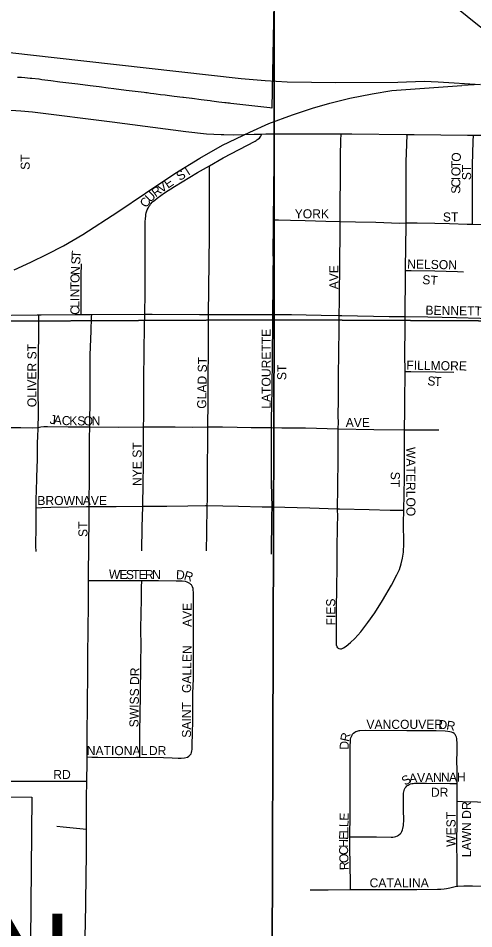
# Model space of a CAD drawing. Extents: x -9.1 to 34, y -3.1 to 22.
# Drawn here: x 3.961 to 4.437, y 19.14 to 20.093 of the extents above; entities that cross this region are included whole.
import ezdxf

# ---------------------------------------------------------------- set-up
doc = ezdxf.new("R2010")
doc.units = 0
for name, color, linetype in [('GM_X_City_Street', 7, 'Continuous'), ('GM_X_City_Street_Text', 7, 'Continuous'), ('GM_X_Corporation', 7, 'Continuous'), ('GM_X_Corporation_Text', 7, 'Continuous'), ('GM_X_Rail_Line', 7, 'Continuous'), ('GM_X_Section', 7, 'Continuous'), ('GM_X_State_Route', 7, 'Continuous')]:
    doc.layers.add(name, color=color, linetype=linetype)

msp = doc.modelspace()

# ---------------------------------------------------------------- linework, layer by layer
at = {"layer": 'GM_X_City_Street'}
for points in [[(4.16087, 19.93855), (4.17537, 19.94691), (4.2085, 19.96427), (4.20954, 19.96483), (4.21052, 19.9655), (4.21156, 19.96621), (4.21304, 19.96755), (4.21386, 19.96851), (4.21448, 19.96951), (4.21581, 19.97174)], [(4.22794, 19.88188), (4.2279, 19.88887), (4.22823, 19.90439), (4.22821, 19.9137), (4.22845, 19.94165), (4.22843, 19.96027), (4.22841, 19.9719)], [(4.29745, 19.88035), (4.29745, 19.88421), (4.29758, 19.89662), (4.29782, 19.92767), (4.29787, 19.94941), (4.29836, 19.96492), (4.29857, 19.97193)], [(4.36671, 19.87867), (4.36667, 19.90228), (4.36673, 19.94262), (4.36723, 19.96124), (4.3675, 19.97124)], [(4.43592, 19.87741), (4.43603, 19.88408), (4.43613, 19.89033), (4.43602, 19.89958), (4.43608, 19.93955), (4.43678, 19.96407), (4.43696, 19.9705)], [(4.09572, 19.89225), (4.09661, 19.89415), (4.09754, 19.89584), (4.09832, 19.89707), (4.09934, 19.89839), (4.10144, 19.90068), (4.10368, 19.9027), (4.1061, 19.90464), (4.11382, 19.91011), (4.1243, 19.91687), (4.14836, 19.93134), (4.16087, 19.93855)], [(4.16001, 19.78304), (4.16023, 19.80993), (4.16091, 19.86603), (4.16097, 19.90967), (4.16088, 19.93458), (4.16087, 19.93855)], [(4.09319, 19.78325), (4.09345, 19.80552), (4.09346, 19.85212), (4.0937, 19.88008), (4.09381, 19.88302), (4.09415, 19.88626), (4.09433, 19.88764), (4.0947, 19.88931), (4.09572, 19.89225)], [(4.22713, 19.78295), (4.22736, 19.81436), (4.22739, 19.82989), (4.22767, 19.83919), (4.22764, 19.84851), (4.22797, 19.87645), (4.22794, 19.88188)], [(4.22794, 19.88188), (4.23317, 19.88179), (4.24552, 19.88159), (4.26093, 19.88133), (4.28252, 19.88059), (4.29745, 19.88035)], [(4.2967, 19.78181), (4.2968, 19.79726), (4.29716, 19.84073), (4.29746, 19.86557), (4.29745, 19.88035)], [(4.29745, 19.88035), (4.31351, 19.87987), (4.33505, 19.87934), (4.35965, 19.87864), (4.36671, 19.87867)], [(4.36588, 19.82907), (4.36629, 19.85583), (4.36672, 19.87439), (4.36671, 19.87867)], [(4.36671, 19.87867), (4.37818, 19.87872), (4.39664, 19.87855), (4.41194, 19.87829), (4.43053, 19.87758), (4.43592, 19.87741)], [(4.43592, 19.87741), (4.44582, 19.87712), (4.44887, 19.8771), (4.45033, 19.87715), (4.45191, 19.87728), (4.45343, 19.87754), (4.45483, 19.87803), (4.45618, 19.87867), (4.45746, 19.87949)], [(4.0267, 19.7829), (4.02667, 19.79032), (4.02662, 19.80862), (4.02665, 19.82387), (4.02719, 19.83608)], [(4.36566, 19.78066), (4.36577, 19.82494), (4.36588, 19.82907)], [(4.36588, 19.82907), (4.37198, 19.82893), (4.39643, 19.82844), (4.40848, 19.82809), (4.42032, 19.82788), (4.4265, 19.82747)], [(3.92629, 19.7819), (3.98068, 19.78246), (3.98245, 19.78248)], [(3.98163, 19.66474), (3.98172, 19.66863), (3.9819, 19.67452), (3.98207, 19.68431), (3.98182, 19.69991), (3.98186, 19.70301), (3.98182, 19.71222), (3.982, 19.71799), (3.98209, 19.72448), (3.98195, 19.73069), (3.98199, 19.73594), (3.98205, 19.74348), (3.98209, 19.74816), (3.98227, 19.75533), (3.98246, 19.76784), (3.98247, 19.77436), (3.98248, 19.77747), (3.98248, 19.78124), (3.98245, 19.78248)], [(3.98245, 19.78248), (3.9847, 19.78251), (4.02034, 19.78287), (4.0267, 19.7829)], [(4.0267, 19.7829), (4.03769, 19.78296)], [(4.03557, 19.66525), (4.03562, 19.66917), (4.03593, 19.69402), (4.03616, 19.74067), (4.03697, 19.76557), (4.03756, 19.77996), (4.03769, 19.78296)], [(4.03769, 19.78296), (4.09319, 19.78325)], [(4.09199, 19.66521), (4.09212, 19.6751), (4.09226, 19.69371), (4.09235, 19.71544), (4.09305, 19.77135), (4.09319, 19.78325)], [(4.09319, 19.78325), (4.10098, 19.78328), (4.15058, 19.78305), (4.16001, 19.78304)], [(4.15928, 19.6652), (4.1594, 19.69154), (4.1596, 19.7102), (4.15975, 19.75072), (4.16001, 19.78304)], [(4.16001, 19.78304), (4.21571, 19.78302), (4.22713, 19.78295)], [(4.22584, 19.66451), (4.22582, 19.6685), (4.22618, 19.69331), (4.22628, 19.69952), (4.22632, 19.70262), (4.22646, 19.71191), (4.22643, 19.71501), (4.22679, 19.72743), (4.22664, 19.73364), (4.22682, 19.74295), (4.22704, 19.77089), (4.22713, 19.78295)], [(4.22713, 19.78295), (4.24671, 19.78284), (4.26218, 19.78255), (4.27766, 19.78236), (4.2967, 19.78181)], [(4.29565, 19.6633), (4.29567, 19.67012), (4.29559, 19.67622), (4.29575, 19.69482), (4.2958, 19.70412), (4.29575, 19.71654), (4.2962, 19.74448), (4.29662, 19.76621), (4.2967, 19.78181)], [(4.2967, 19.78181), (4.29934, 19.78173), (4.34897, 19.78091), (4.36566, 19.78066)], [(4.36552, 19.72333), (4.36538, 19.74122), (4.36563, 19.76915), (4.36566, 19.78066)], [(4.36566, 19.78066), (4.38924, 19.78031), (4.41939, 19.77962), (4.44389, 19.77921), (4.47645, 19.7787)], [(4.36492, 19.66215), (4.36508, 19.68294), (4.36522, 19.69512), (4.36555, 19.71954), (4.36552, 19.72333)], [(4.36552, 19.72333), (4.37163, 19.72323), (4.39722, 19.72281), (4.4164, 19.72265)], [(3.92585, 19.66479), (3.93605, 19.66472), (3.96356, 19.66453), (3.97601, 19.66448), (3.98163, 19.66474)], [(3.97966, 19.58071), (3.97966, 19.58161), (3.97966, 19.59097), (3.9799, 19.5972), (3.98026, 19.61278), (3.98087, 19.6314), (3.98083, 19.63764), (3.981, 19.64385), (3.98109, 19.64963), (3.98127, 19.65434), (3.98163, 19.66474)], [(3.98163, 19.66474), (3.98461, 19.66528), (3.98757, 19.66555), (3.99133, 19.66555), (4.01299, 19.66547), (4.03475, 19.66525), (4.03557, 19.66525)], [(4.03516, 19.58195), (4.03526, 19.61636), (4.03538, 19.63192), (4.03545, 19.65366), (4.03557, 19.66525)], [(4.03557, 19.66525), (4.06581, 19.66494), (4.09199, 19.66521)], [(4.09104, 19.58223), (4.09139, 19.60657), (4.09176, 19.62513), (4.09185, 19.6534), (4.09199, 19.66521)], [(4.09199, 19.66521), (4.09688, 19.66526), (4.12485, 19.66534), (4.14346, 19.66519), (4.15928, 19.6652)], [(4.15857, 19.5829), (4.15875, 19.58877), (4.15885, 19.62304), (4.15922, 19.65106), (4.15928, 19.6652)], [(4.15928, 19.6652), (4.17444, 19.66522), (4.18984, 19.66492), (4.2045, 19.66466), (4.21475, 19.66463), (4.22584, 19.66451)], [(4.22628, 19.58154), (4.22629, 19.58159), (4.22564, 19.60641), (4.22588, 19.64367), (4.22584, 19.66451)], [(4.22584, 19.66451), (4.23649, 19.66439), (4.26132, 19.66419), (4.29547, 19.6633), (4.29565, 19.6633)], [(4.29482, 19.57966), (4.29489, 19.58433), (4.29495, 19.58842), (4.29501, 19.59314), (4.29506, 19.59698), (4.29514, 19.60228), (4.2952, 19.60822), (4.29526, 19.61467), (4.29531, 19.61971), (4.29534, 19.62367), (4.29538, 19.62776), (4.29542, 19.63171), (4.29546, 19.63645), (4.2955, 19.6413), (4.29554, 19.64526), (4.2956, 19.65161), (4.29565, 19.66086), (4.29565, 19.6633)], [(4.29565, 19.6633), (4.33272, 19.66265), (4.36492, 19.66215)], [(4.36401, 19.57821), (4.36486, 19.61181), (4.36484, 19.65206), (4.36492, 19.66215)], [(4.36492, 19.66215), (4.36991, 19.66207), (4.3915, 19.6624), (4.4008, 19.6623)], [(3.97974, 19.53496), (3.9794, 19.54068), (3.9794, 19.54494), (3.97949, 19.55675), (3.97967, 19.56077), (3.97966, 19.56529), (3.9797, 19.56915), (3.97966, 19.58071)], [(3.97966, 19.58071), (3.98566, 19.58093), (3.99497, 19.58127), (4.03232, 19.58193), (4.03516, 19.58195)], [(4.0344, 19.50475), (4.03445, 19.51058), (4.03513, 19.56969), (4.03516, 19.58195)], [(4.03516, 19.58195), (4.06345, 19.58211), (4.09104, 19.58223)], [(4.09005, 19.53552), (4.0906, 19.56032), (4.09103, 19.58204), (4.09104, 19.58223)], [(4.09104, 19.58223), (4.11636, 19.58235), (4.13816, 19.58263), (4.15683, 19.58293), (4.15857, 19.5829)], [(4.15791, 19.53577), (4.15798, 19.55453), (4.15857, 19.5829)], [(4.15857, 19.5829), (4.19106, 19.58227), (4.21596, 19.5818), (4.22628, 19.58154)], [(4.2256, 19.53214), (4.22579, 19.53817), (4.22582, 19.54187), (4.22586, 19.54542), (4.2259, 19.54995), (4.22594, 19.55367), (4.22613, 19.56298), (4.22595, 19.57196), (4.22628, 19.58154)], [(4.22628, 19.58154), (4.26571, 19.58055), (4.29482, 19.57966)], [(4.29835, 19.43274), (4.2967, 19.43312), (4.29593, 19.43343), (4.29508, 19.43405), (4.29427, 19.43522), (4.29391, 19.43683), (4.29376, 19.43846), (4.29371, 19.4413), (4.29374, 19.45372), (4.29367, 19.45675), (4.29369, 19.45976), (4.2936, 19.46584), (4.29369, 19.47511), (4.29402, 19.49684), (4.29433, 19.51855), (4.29433, 19.53717), (4.29489, 19.56199), (4.29498, 19.5713), (4.29482, 19.57966)], [(4.29482, 19.57966), (4.29682, 19.5796), (4.32792, 19.57873), (4.34971, 19.57831), (4.35465, 19.57834), (4.36401, 19.57821)], [(4.29835, 19.43274), (4.3011, 19.43409), (4.30368, 19.43577), (4.3085, 19.43959), (4.31295, 19.44385), (4.31912, 19.45073), (4.32665, 19.4605), (4.33369, 19.47062), (4.3419, 19.48366), (4.3512, 19.49964), (4.35696, 19.51054), (4.35952, 19.51614), (4.36151, 19.52197), (4.3629, 19.52797), (4.36372, 19.53407), (4.36409, 19.5433), (4.36383, 19.56487), (4.36401, 19.57821)], [(4.03279, 19.32007), (4.03285, 19.34259), (4.03357, 19.40793), (4.03381, 19.42659), (4.03419, 19.47947), (4.0344, 19.50475)], [(4.0344, 19.50475), (4.04214, 19.5047), (4.06392, 19.50453), (4.08998, 19.50451)], [(4.08808, 19.31959), (4.08807, 19.32443), (4.08805, 19.33125), (4.08803, 19.336), (4.08802, 19.33997), (4.08815, 19.34918), (4.08825, 19.36154), (4.08891, 19.41407), (4.08915, 19.42019), (4.08937, 19.43568), (4.08907, 19.45421), (4.08975, 19.48506), (4.0899, 19.49743), (4.08998, 19.50451)], [(4.08998, 19.50451), (4.1075, 19.5045), (4.12617, 19.50434), (4.13237, 19.50413), (4.13542, 19.50373), (4.13724, 19.50319), (4.13844, 19.50263), (4.13992, 19.50172), (4.14152, 19.50056)], [(4.13784, 19.31979), (4.13938, 19.32071), (4.14078, 19.32203), (4.14162, 19.32323), (4.14218, 19.32463), (4.14245, 19.32624), (4.1426, 19.32785), (4.14288, 19.3308), (4.14327, 19.34652), (4.14344, 19.35575), (4.14346, 19.3681), (4.14357, 19.37722), (4.14355, 19.38653), (4.14405, 19.40199), (4.14422, 19.42991), (4.144, 19.43921), (4.14405, 19.45782), (4.14431, 19.47951), (4.14418, 19.49187), (4.14389, 19.49498), (4.14365, 19.49623), (4.14318, 19.49784), (4.14256, 19.49932), (4.14214, 19.49998), (4.14152, 19.50056)], [(4.30784, 19.23645), (4.30789, 19.25968), (4.30794, 19.28137), (4.30804, 19.31234), (4.30808, 19.32159), (4.3081, 19.33078), (4.3084, 19.33698), (4.30852, 19.33843), (4.30881, 19.34002), (4.30931, 19.34154), (4.30996, 19.34285), (4.31062, 19.34379)], [(4.31062, 19.34379), (4.31165, 19.34496), (4.31274, 19.3458), (4.31406, 19.34653), (4.31539, 19.34712), (4.31638, 19.34747), (4.31746, 19.34767), (4.3183, 19.34772), (4.32442, 19.348), (4.3674, 19.34771), (4.39806, 19.34762), (4.40723, 19.34732), (4.41028, 19.34709), (4.41215, 19.34676), (4.41353, 19.34636), (4.41533, 19.34556)], [(4.41986, 19.29228), (4.41982, 19.29724), (4.4199, 19.30659), (4.41976, 19.31596), (4.4198, 19.32532), (4.42001, 19.33118), (4.41988, 19.33475), (4.41967, 19.33784), (4.41943, 19.33926), (4.41913, 19.34084), (4.41865, 19.34205), (4.41774, 19.3436), (4.41686, 19.34455), (4.41533, 19.34556)], [(4.03257, 19.29478), (4.03278, 19.31459), (4.03279, 19.32007)], [(4.03279, 19.32007), (4.03767, 19.3199), (4.04394, 19.31969), (4.06593, 19.3194), (4.08457, 19.31959), (4.08808, 19.31959)], [(4.08808, 19.31959), (4.1127, 19.31954), (4.12201, 19.31909), (4.12817, 19.31882), (4.13139, 19.3186), (4.13472, 19.31888), (4.13784, 19.31979)], [(3.84406, 19.29469), (3.92161, 19.29464), (3.95919, 19.29466), (4.0249, 19.29477), (4.03257, 19.29478)], [(4.03216, 19.24434), (4.03238, 19.27728), (4.03257, 19.29478)], [(4.30784, 19.23645), (4.31411, 19.23641), (4.33564, 19.23624), (4.35107, 19.23608), (4.35273, 19.23606), (4.35432, 19.23631), (4.35584, 19.2367), (4.35749, 19.23738), (4.35867, 19.23805), (4.36018, 19.2394), (4.36122, 19.2406), (4.36219, 19.24209), (4.36285, 19.24364), (4.36325, 19.24526), (4.36367, 19.24839), (4.36413, 19.25463), (4.36386, 19.2639), (4.36366, 19.27615), (4.36378, 19.27907), (4.36397, 19.28214), (4.36438, 19.28504), (4.36482, 19.28639), (4.36553, 19.28759), (4.36646, 19.28874), (4.36738, 19.28962), (4.36861, 19.29044), (4.36986, 19.29123), (4.37116, 19.29175), (4.37254, 19.29214), (4.37391, 19.29234), (4.37542, 19.29249), (4.38771, 19.29256), (4.41233, 19.29234), (4.41986, 19.29228)], [(4.41992, 19.2736), (4.41995, 19.28163), (4.41986, 19.29228)], [(4.41992, 19.18461), (4.41991, 19.18983), (4.4199, 19.19427), (4.41978, 19.20363), (4.41978, 19.21611), (4.41972, 19.22253), (4.41986, 19.25978), (4.41992, 19.2736)], [(4.41992, 19.2736), (4.42568, 19.27341), (4.44106, 19.2729), (4.45344, 19.27272), (4.4628, 19.27276), (4.46495, 19.27277), (4.46724, 19.27284), (4.46882, 19.27299), (4.47084, 19.27341), (4.47394, 19.27408)], [(4.00124, 19.2476), (4.00782, 19.24689), (4.03216, 19.24434)], [(4.03094, 19.12826), (4.03095, 19.13452), (4.0313, 19.14389), (4.03213, 19.21891), (4.03216, 19.24434)], [(4.3084, 19.18113), (4.3083, 19.18844), (4.30782, 19.22562), (4.30784, 19.23645)], [(4.26634, 19.18093), (4.28493, 19.18104), (4.3084, 19.18113)], [(4.3084, 19.18113), (4.32511, 19.18118), (4.35297, 19.18118), (4.37771, 19.18112), (4.39939, 19.18158), (4.40287, 19.18172), (4.40641, 19.18197), (4.40871, 19.18233), (4.41235, 19.18296), (4.41524, 19.1837), (4.4178, 19.1843), (4.41992, 19.18461)], [(4.41992, 19.18461), (4.4208, 19.18474), (4.42689, 19.18504), (4.43609, 19.18525), (4.46699, 19.18451), (4.47366, 19.18435)]]:
    msp.add_lwpolyline(points, dxfattribs=at)
at = {"layer": 'GM_X_Corporation'}
for points in [[(4.23107, 20.25518), (4.22608, 19.99885), (4.22407, 19.99908), (4.18323, 20.00378), (4.18172, 20.00396), (4.18022, 20.00413), (4.17997, 20.00416), (4.17848, 20.00433), (4.17699, 20.0045), (4.17081, 20.00522), (4.16333, 20.00608), (4.16143, 20.00635), (4.15202, 20.00755), (4.14263, 20.00875), (4.14256, 20.00876), (4.13355, 20.00981), (4.13322, 20.00986), (4.13318, 20.00986), (4.12383, 20.01106), (4.12379, 20.01106), (4.11669, 20.01198), (4.11665, 20.01198), (4.11443, 20.01227), (4.1144, 20.01227), (4.10955, 20.01289), (4.10951, 20.0129), (4.10504, 20.01347), (4.105, 20.01347), (4.10259, 20.01378), (4.10256, 20.01379), (4.09921, 20.01422), (4.09918, 20.01422), (4.09564, 20.01468), (4.09414, 20.01487), (4.09264, 20.01506), (4.08612, 20.01587), (4.08331, 20.01622), (4.07372, 20.01742), (4.06073, 20.01904), (4.05486, 20.01978), (4.04559, 20.02094), (4.036, 20.02213), (4.02318, 20.02373), (4.01378, 20.02491), (4.00438, 20.02608), (3.99498, 20.02726), (3.98559, 20.02843), (3.98276, 20.02904), (3.98256, 20.02906), (3.97522, 20.02979), (3.97343, 20.02997), (3.96764, 20.03044), (3.96433, 20.03071), (3.96004, 20.03097)], [(3.84232, 19.27891), (3.97523, 19.27787), (3.97257, 19.01533), (3.97172, 18.88312), (3.97024, 18.77889), (3.71873, 18.78737)]]:
    msp.add_lwpolyline(points, dxfattribs=at)
at = {"layer": 'GM_X_Rail_Line'}
for points in [[(2.6, 20.20616), (2.61878, 20.20477), (2.65021, 20.20366), (2.67105, 20.20276), (2.70793, 20.19875), (3.62422, 20.09412), (3.99829, 20.05166), (4.19407, 20.02982), (4.21899, 20.02788), (4.24227, 20.02625), (4.29308, 20.02562), (4.35791, 20.026), (4.38531, 20.02687), (4.40008, 20.0265), (4.44452, 20.02352)], [(3.95675, 19.82971), (3.97406, 19.83749), (3.99118, 19.84595), (4.00819, 19.85489), (4.02832, 19.86666), (4.06508, 19.89029), (4.09406, 19.90994), (4.1247, 19.93036), (4.15066, 19.9466), (4.17458, 19.96011), (4.20317, 19.97383), (4.22282, 19.98277), (4.24781, 19.99172), (4.26872, 19.99892), (4.28671, 20.00397), (4.30762, 20.00932), (4.33105, 20.01389), (4.35177, 20.0171), (4.42483, 20.02258)], [(4.44452, 20.02352), (4.42483, 20.02258)]]:
    msp.add_lwpolyline(points, dxfattribs=at)
at = {"layer": 'GM_X_Section'}
for points in [[(3.25407, 20.77641), (4.22892, 20.78268), (4.2285, 19.77719), (3.23473, 19.77259)], [(4.22892, 20.78268), (5.2279, 20.77322), (5.226, 19.77229), (4.2285, 19.77719)], [(3.23473, 19.77259), (4.2285, 19.77719), (4.22542, 18.77097), (3.22195, 18.78578)], [(4.2285, 19.77719), (5.226, 19.77229), (5.22068, 18.771), (4.22542, 18.77097)]]:
    msp.add_lwpolyline(points, close=True, dxfattribs=at)
at = {"layer": 'GM_X_State_Route'}
for points in [[(4.23107, 20.25518), (4.25901, 20.23288), (4.29774, 20.20173), (4.35591, 20.15507), (4.37889, 20.13658), (4.414, 20.10833), (4.4377, 20.08918), (4.45266, 20.07709), (4.47222, 20.06172), (4.4829, 20.05327), (4.49795, 20.04136), (4.50576, 20.03497), (4.51271, 20.02947), (4.52002, 20.0237), (4.52329, 20.02122), (4.52859, 20.01721), (4.541, 20.00846), (4.56139, 19.9947), (4.57197, 19.98778), (4.57827, 19.98368), (4.58251, 19.98056), (4.58588, 19.97764)], [(3.73681, 19.99533), (3.73858, 19.99638), (3.74023, 19.99711), (3.74206, 19.99763), (3.74338, 19.99789), (3.74944, 19.9984), (3.75868, 19.9986), (3.78973, 19.99809), (3.81147, 19.99766), (3.84875, 19.99708), (3.89845, 19.99706), (3.90328, 19.99702), (3.9295, 19.99682), (3.95122, 19.99661), (3.95841, 19.9963), (3.96357, 19.99608), (3.9759, 19.99492), (4.05907, 19.98436), (4.13607, 19.97443), (4.15771, 19.97204), (4.17326, 19.97115), (4.17584, 19.9711)], [(4.17584, 19.9711), (4.18573, 19.97087), (4.20745, 19.97165), (4.21581, 19.97174), (4.21987, 19.97179), (4.22841, 19.9719), (4.24159, 19.97207), (4.29857, 19.97193), (4.30991, 19.9719), (4.3665, 19.97125)], [(4.3665, 19.97125), (4.3675, 19.97124), (4.37512, 19.97115), (4.43089, 19.97052), (4.43696, 19.9705), (4.44585, 19.97047), (4.46523, 19.97051), (4.47404, 19.97087), (4.48078, 19.97116), (4.49113, 19.97166), (4.4965, 19.97212), (4.50558, 19.9729), (4.53965, 19.97525), (4.55824, 19.97671), (4.57384, 19.97787), (4.58588, 19.97764)]]:
    msp.add_lwpolyline(points, dxfattribs=at)

# ---------------------------------------------------------------- texts
at = {"layer": 'GM_X_City_Street_Text'}
for s, rotation, p in [('ST', 90, (3.97286, 19.93425)), ('O', 86.39093, (4.42347, 19.94243)), ('T', 89.58089, (4.42343, 19.93591)), ('ST', 32.73207, (4.12988, 19.92242)), ('O', 89.57614, (4.42337, 19.92757)), ('ST', 90, (4.43452, 19.92342)), ('V', 34.60531, (4.11062, 19.90964)), ('E', 34.56902, (4.11748, 19.91437)), ('C', 89.56281, (4.42328, 19.9159)), ('I', 89.56296, (4.42334, 19.9234)), ('U', 44.11907, (4.0989, 19.89968)), ('R', 36.12199, (4.10462, 19.90525)), ('S', 89.59016, (4.42323, 19.90924)), ('C', 54.85477, (4.09489, 19.8939)), ('YORK', 0.00001, (4.25001, 19.88354)), ('ST', 0.00001, (4.40501, 19.8802)), ('T', 86.41804, (4.02598, 19.84158)), ('S', 86.39127, (4.02556, 19.83492)), ('NELSON', 358.96018, (4.36759, 19.83103)), ('N', 87.04809, (4.02498, 19.82413)), ('AVE', 90, (4.29573, 19.80925)), ('O', 89.47536, (4.02491, 19.8159)), ('T', 90, (4.02491, 19.80926)), ('ST', 356.18786, (4.38321, 19.81478)), ('N', 89.98125, (4.0249, 19.80092)), ('I', 89.95628, (4.0249, 19.79675)), ('C', 89.9757, (4.0249, 19.78259)), ('L', 89.98213, (4.0249, 19.79009)), ('BENNETT', 359.08765, (4.38671, 19.7827)), ('LATOURETTE', 90, (4.2249, 19.68426)), ('OLIVER ST', 90, (3.9799, 19.68592)), ('GLAD ST', 89.0145, (4.1574, 19.68421)), ('FILLMORE', 359.15624, (4.36676, 19.72521)), ('ST', 90, (4.24119, 19.71426)), ('S', 354.44439, (4.38844, 19.709)), ('T', 358.02171, (4.39572, 19.70831)), ('J', 355.31624, (3.9935, 19.66853)), ('A', 355.29625, (3.99765, 19.66819)), ('C', 356.14096, (4.00611, 19.66749)), ('K', 359.36207, (4.01417, 19.66696)), ('S', 359.99563, (4.02262, 19.66687)), ('O', 359.99285, (4.02929, 19.66687)), ('N', 359.99285, (4.03762, 19.66687)), ('AVE', 0.00001, (4.30335, 19.6652)), ('NYE ST', 90, (4.0899, 19.60342)), ('WATERLOO', 270, (4.3668, 19.64426)), ('ST', 270, (4.3505, 19.61842)), ('BROWN', 0.00001, (3.98085, 19.58354)), ('AVE', 0.00001, (4.02835, 19.58354)), ('ST', 90, (4.03323, 19.55009)), ('W', 356.06291, (4.05523, 19.50686)), ('E', 359.53103, (4.06666, 19.50609)), ('S', 359.99563, (4.07341, 19.50604)), ('T', 359.99563, (4.08008, 19.50604)), ('E', 359.99563, (4.08674, 19.50604)), ('R', 359.99406, (4.09341, 19.50604)), ('N', 359.99285, (4.10091, 19.50604)), ('D', 357.85787, (4.12575, 19.50604)), ('R', 343.27051, (4.13345, 19.50583)), ('FIES', 90, (4.2924, 19.45759)), ('AVE', 90, (4.1424, 19.45592)), ('GALLEN', 89.14212, (4.14156, 19.38678)), ('SWISS DR', 89.12045, (4.08656, 19.35088)), ('SAINT', 90, (4.14156, 19.34009)), ('VANCOUVER', 0.00001, (4.32501, 19.34938)), ('D', 355.64655, (4.40009, 19.34937)), ('R', 350.92891, (4.4082, 19.34876)), ('R', 77.24201, (4.30659, 19.33537)), ('NATIONAL', 0.00001, (4.03251, 19.32187)), ('DR', 0.00001, (4.09751, 19.32187)), ('D', 89.43164, (4.30657, 19.32756)), ('RD', 0.00001, (3.99751, 19.29687)), ('A', 5.16475, (4.37001, 19.29285)), ('V', 1.02732, (4.37813, 19.29359)), ('A', 0.83063, (4.38646, 19.29374)), ('N', 0.80878, (4.39479, 19.29386)), ('N', 0.8154, (4.40312, 19.29397)), ('A', 0.80878, (4.41145, 19.29409)), ('H', 0.8154, (4.41978, 19.29421)), ('S', 31.56813, (4.36542, 19.28972)), ('DR', 0.00001, (4.39251, 19.27826)), ('LAWN DR', 90, (4.43452, 19.21509)), ('E', 88.68873, (4.30635, 19.25321)), ('WEST', 90, (4.41823, 19.22592)), ('L', 88.68873, (4.30605, 19.23987)), ('L', 88.7128, (4.3062, 19.24654)), ('E', 88.71603, (4.3059, 19.23321)), ('C', 91.57901, (4.30603, 19.21751)), ('H', 89.49721, (4.30582, 19.22491)), ('O', 91.95385, (4.30631, 19.20919)), ('R', 91.94314, (4.30657, 19.2017)), ('CATALINA', 0.00001, (4.32834, 19.18354))]:
    msp.add_text(s, height=0.00947, rotation=rotation, dxfattribs=at).set_placement(p)
at = {"layer": 'GM_X_Corporation_Text'}
msp.add_text('MARION', height=0.094697, rotation=0.00001, dxfattribs=at).set_placement((3.51088, 19.06148))

doc.saveas('drawing.dxf')
